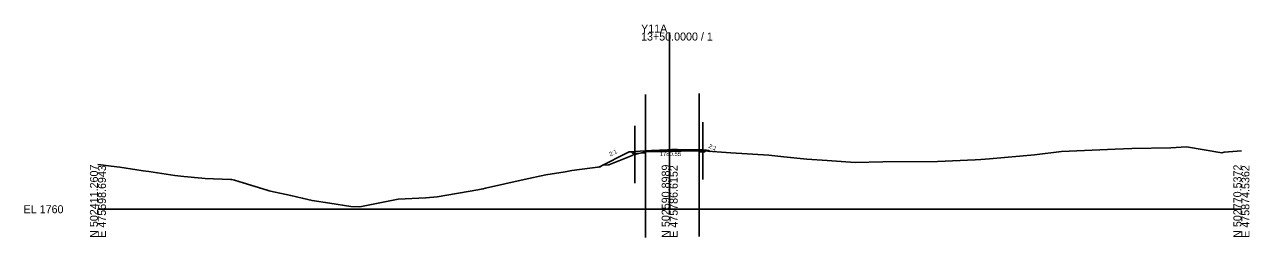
# Model space of a CAD drawing. Extents: x -26 to 403, y -10 to 5098.
# Drawn here: x -25.7 to 402.8, y 3490.1 to 3564.6 of the extents above; entities that cross this region are included whole.
import ezdxf

# ---------------------------------------------------------------- set-up
doc = ezdxf.new("R2010")
doc.units = 0
for name, color, linetype in [('Exist Cross Section Cell', 7, 'Continuous'), ('Exist XS Center Line Elevation Label', 7, 'Continuous'), ('Exist XS Ground Line', 7, 'Continuous'), ('Prop XS Earthwork Shape', 7, 'Continuous'), ('Prop XS Finish Grade', 7, 'Continuous'), ('Prop XS Finish Grade Earthwork', 7, 'Continuous'), ('Prop XS Finish Grade Pavement', 7, 'Continuous'), ('Prop XS Pvmt Edge Slope', 7, 'Continuous'), ('Prop XS Shoulder Borrow Shape', 7, 'Continuous'), ('Prop XS Side Slope Text', 7, 'Continuous'), ('Prop XS Subgrade Earthwork', 7, 'Continuous'), ('Scratch_Level_1', 7, 'Continuous'), ('Scratch_Level_5', 7, 'Continuous'), ('Scratch_Level_6', 7, 'Continuous')]:
    doc.layers.add(name, color=color, linetype=linetype)

msp = doc.modelspace()

# ---------------------------------------------------------------- linework, layer by layer
at = {"layer": 'Exist Cross Section Cell'}
for p, q in [((200, 3500), (200, 3561.78)), ((0, 3500), (200, 3500)), ((200, 3500), (400, 3500))]:
    msp.add_line(p, q, dxfattribs=at)
at = {"layer": 'Exist XS Ground Line'}
msp.add_lwpolyline([(0, 3515.64), (1.02, 3515.5), (4.66, 3515.07), (7.61, 3514.74), (13.64, 3513.79), (15.08, 3513.57), (15.79, 3513.46), (17.86, 3513.17), (26.93, 3511.85), (30.04, 3511.5), (36.39, 3510.82), (37.51, 3510.77), (46.37, 3510.42), (46.87, 3510.36), (47.81, 3510.15), (50.84, 3509.25), (59.14, 3506.7), (59.94, 3506.45), (60.33, 3506.36), (67.42, 3504.77), (71.47, 3503.88), (74.9, 3503.03), (81.09, 3502.17), (88.49, 3500.93), (91.61, 3500.83), (105.04, 3503.5), (114.72, 3503.97), (118.63, 3504.37), (132.89, 3506.78), (134.1, 3506.97), (134.78, 3507.11), (135.52, 3507.32), (149.13, 3510.43), (156.72, 3512.08), (163.39, 3513.05), (165.82, 3513.54), (175.72, 3514.82), (176.48, 3515.35), (178.76, 3515.47), (186.89, 3518.83), (187.26, 3519.03), (187.79, 3519.17), (191.5, 3520.06), (192.08, 3520.16), (192.49, 3520.18), (193.64, 3520.24), (194.23, 3520.27), (195.41, 3520.33), (196.41, 3520.38), (197.95, 3520.45), (199.21, 3520.51), (199.63, 3520.53), (200.09, 3520.55), (200.66, 3520.58), (201.95, 3520.59), (202.77, 3520.59), (204.72, 3520.57), (206.75, 3520.54), (207.54, 3520.53), (209.69, 3520.49), (210.17, 3520.47), (211.69, 3520.43), (221.37, 3519.69), (234.64, 3518.85), (239.93, 3518.37), (248.01, 3517.49), (255.12, 3517.01), (264.94, 3516.38), (274.52, 3516.52), (293.64, 3516.67), (306.9, 3517.23), (308.9, 3517.41), (311.87, 3517.57), (327.59, 3519.07), (337.06, 3520.19), (355.82, 3521), (361.7, 3521.26), (375.36, 3521.42), (380.76, 3521.87), (393.15, 3519.77), (393.97, 3519.92), (400, 3520.45)], dxfattribs=at)
at = {"layer": 'Prop XS Earthwork Shape'}
for points in [[(175.26, 3514.76), (175.72, 3514.82), (176.48, 3515.35), (178.76, 3515.47), (186.89, 3518.83), (187.26, 3519.03), (187.79, 3519.17), (189.72, 3519.63), (187.79, 3519.52), (187.11, 3519.51), (186.53, 3520.09), (185.79, 3520.03)], [(189.72, 3519.63), (191.55, 3519.74), (191.55, 3520.07), (191.5, 3520.06)], [(210.33, 3520.47), (211.69, 3520.43), (212.6, 3520.36), (212.27, 3520.03), (211.59, 3520.04), (210.33, 3520.06)], [(212.6, 3520.36), (214.21, 3520.24), (213.59, 3520.55), (212.85, 3520.61)]]:
    msp.add_lwpolyline(points, close=True, dxfattribs=at)
at = {"layer": 'Prop XS Finish Grade'}
for p, q in [((187.79, 3520.19), (186.53, 3520.09)), ((211.59, 3520.71), (212.85, 3520.61))]:
    msp.add_line(p, q, dxfattribs=at)
at = {"layer": 'Prop XS Finish Grade Earthwork'}
for p, q in [((185.79, 3520.03), (175.26, 3514.76)), ((186.53, 3520.09), (185.79, 3520.03)), ((212.85, 3520.61), (213.59, 3520.55)), ((213.59, 3520.55), (214.21, 3520.24))]:
    msp.add_line(p, q, dxfattribs=at)
at = {"layer": 'Prop XS Finish Grade Pavement'}
for points in [[(187.79, 3520.19), (191.55, 3520.38)], [(191.55, 3520.38), (193.62, 3520.49), (194.22, 3520.52), (195.4, 3520.58), (196.4, 3520.63), (197.94, 3520.7), (199.2, 3520.76), (199.62, 3520.78), (200.08, 3520.8), (200.66, 3520.83), (201.95, 3520.84), (202.77, 3520.84), (204.72, 3520.82), (206.75, 3520.79), (207.54, 3520.78), (211.59, 3520.71)]]:
    msp.add_lwpolyline(points, dxfattribs=at)
at = {"layer": 'Prop XS Pvmt Edge Slope'}
for p, q in [((187.79, 3520.19), (187.11, 3519.51)), ((211.59, 3520.71), (212.27, 3520.03))]:
    msp.add_line(p, q, dxfattribs=at)
at = {"layer": 'Prop XS Shoulder Borrow Shape'}
for points in [[(187.11, 3519.51), (186.53, 3520.09), (187.79, 3520.19)], [(211.59, 3520.71), (212.85, 3520.61), (212.27, 3520.03)]]:
    msp.add_lwpolyline(points, close=True, dxfattribs=at)
at = {"layer": 'Prop XS Subgrade Earthwork'}
for p, q in [((187.11, 3519.51), (186.53, 3520.09)), ((187.79, 3519.52), (187.11, 3519.51)), ((191.55, 3520.07), (191.55, 3519.74)), ((210.33, 3520.06), (210.33, 3520.47)), ((211.59, 3520.04), (212.27, 3520.03)), ((212.27, 3520.03), (212.85, 3520.61))]:
    msp.add_line(p, q, dxfattribs=at)
for points in [[(187.79, 3519.52), (191.55, 3519.74)], [(210.33, 3520.06), (211.59, 3520.04)]]:
    msp.add_lwpolyline(points, dxfattribs=at)
at = {"layer": 'Scratch_Level_1'}
for p, q in [((191.55, 3540.12), (191.55, 3490.12)), ((210.33, 3540.47), (210.33, 3490.47))]:
    msp.add_line(p, q, dxfattribs=at)
at = {"layer": 'Scratch_Level_5'}
for p, q in [((187.79, 3529.17), (187.79, 3509.17)), ((211.59, 3530.43), (211.59, 3510.43))]:
    msp.add_line(p, q, dxfattribs=at)
at = {"layer": 'Scratch_Level_6'}
msp.add_line((191.55, 3520.07), (210.33, 3520.47), dxfattribs=at)

# ---------------------------------------------------------------- texts
at = {"layer": 'Exist Cross Section Cell'}
for s, p in [('Y11A', (190, 3561.78)), ('13+50.0000 / 1', (190, 3558.98)), ('EL 1760', (-26, 3498.6))]:
    msp.add_text(s, height=2.8, dxfattribs=at).set_placement(p)
for s, p in [('N 502411.2607', (0, 3490)), ('E 475698.6943', (2.8, 3490)), ('N 502590.8989', (200, 3490)), ('E 475786.6152', (202.8, 3490)), ('N 502770.5372', (400, 3490)), ('E 475874.5362', (402.8, 3490))]:
    msp.add_text(s, height=2.8, rotation=90, dxfattribs=at).set_placement(p)
at = {"layer": 'Exist XS Center Line Elevation Label'}
msp.add_text('1780.55', height=1.5, dxfattribs=at).set_placement((196.49, 3518.6))
at = {"layer": 'Prop XS Side Slope Text'}
for rotation, p in [(335.2378, (213.45, 3521.58)), (26.5651, (179.26, 3518.44))]:
    msp.add_text('2:1', height=1.5, rotation=rotation, dxfattribs=at).set_placement(p)

doc.saveas('drawing.dxf')
